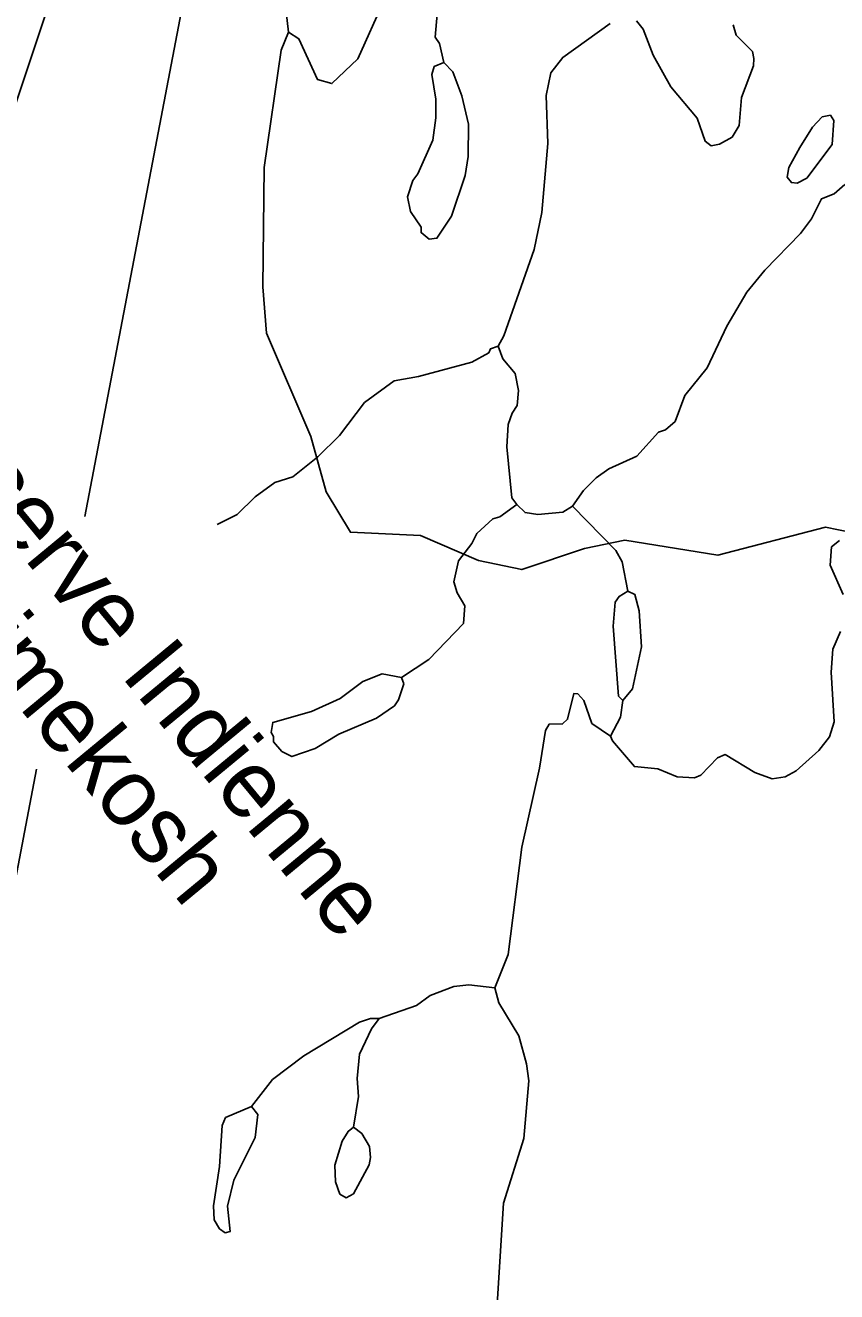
# Model space of a CAD drawing. Extents: x 347312 to 350503, y 6073086 to 6076432.
# Drawn here: x 349676.6 to 349727.5, y 6073873.7 to 6073953.1 of the extents above; entities that cross this region are included whole.
import ezdxf

# ---------------------------------------------------------------- set-up
doc = ezdxf.new("R2010")
doc.units = 0
doc.layers.add('Level 63', color=7, linetype='Continuous')

msp = doc.modelspace()

# ---------------------------------------------------------------- linework, layer by layer
at = {"layer": 'Level 63'}
msp.add_line((349711.71, 6073920.299), (349714.224, 6073920.823), dxfattribs=at)
for points in [[(349680.344, 6073922.306), (349692.276, 6073984.699), (349619.957, 6073998.53), (349601.588, 6073902.476), (349673.907, 6073888.646), (349677.31, 6073906.439)], [(349670.288, 6073937.763), (349671.84, 6073937.31), (349672.811, 6073938.62), (349679.527, 6073958.794), (349681.5, 6073961.168), (349682.809, 6073963.56), (349683.562, 6073964.047), (349684.56, 6073964.294), (349688.619, 6073963.002), (349690.54, 6073961.809), (349691.83, 6073959.629), (349692.683, 6073956.562), (349693.14, 6073952.692)], [(349699.131, 6073954.719), (349697.489, 6073951.034), (349695.853, 6073949.468), (349694.944, 6073949.726), (349693.789, 6073952.283), (349693.14, 6073952.692)], [(349702.532, 6073954.534), (349702.34, 6073952.375), (349702.597, 6073951.982), (349702.883, 6073950.798)], [(349721.028, 6073953.162), (349721.224, 6073952.503), (349722.254, 6073951.474), (349722.325, 6073951.042), (349722.303, 6073950.59), (349721.554, 6073948.588), (349721.411, 6073946.848), (349720.962, 6073946.113), (349720.182, 6073945.659), (349719.657, 6073945.569), (349719.267, 6073945.856), (349718.77, 6073947.308), (349717.119, 6073949.257), (349716.021, 6073951.263), (349715.392, 6073952.881), (349714.97, 6073953.415)], [(349693.14, 6073952.692), (349692.675, 6073951.565), (349691.605, 6073944.209), (349691.516, 6073936.709)], [(349713.315, 6073953.245), (349710.339, 6073951.108), (349709.59, 6073950.136), (349709.303, 6073948.716), (349709.406, 6073945.705), (349709.023, 6073941.389), (349708.538, 6073939.053), (349706.635, 6073933.642), (349706.286, 6073932.986), (349706.587, 6073932.193), (349707.359, 6073931.286), (349707.566, 6073930.201), (349707.488, 6073929.272), (349707.159, 6073928.795)], [(349702.883, 6073950.798), (349702.277, 6073950.535), (349702.128, 6073950.038), (349702.372, 6073948.495), (349702.385, 6073947.312), (349702.191, 6073945.911), (349701.25, 6073943.81), (349700.928, 6073943.394), (349700.597, 6073942.372), (349700.791, 6073941.441), (349701.464, 6073940.454), (349701.455, 6073940.122), (349701.951, 6073939.701), (349702.443, 6073939.764), (349703.361, 6073941.141), (349704.206, 6073943.708), (349704.405, 6073944.896), (349704.43, 6073946.922), (349704.001, 6073948.699), (349703.451, 6073950.216), (349702.883, 6073950.798)], [(349727.149, 6073947.48), (349727.353, 6073947.154), (349727.238, 6073945.653), (349725.659, 6073943.535), (349725.046, 6073943.213), (349724.687, 6073943.255), (349724.423, 6073943.589), (349724.526, 6073944.213), (349725.218, 6073945.465), (349726.002, 6073946.736), (349726.623, 6073947.39), (349727.149, 6073947.48)], [(349707.159, 6073928.795), (349706.923, 6073928.066), (349706.822, 6073926.684), (349707.143, 6073923.467), (349707.46, 6073923.066), (349707.975, 6073922.552), (349708.778, 6073922.428), (349710.341, 6073922.579), (349710.961, 6073922.96), (349711.65, 6073923.94), (349712.439, 6073924.726), (349713.233, 6073925.3), (349714.991, 6073926.094), (349716.348, 6073927.601), (349716.787, 6073927.732), (349717.395, 6073928.267), (349718.009, 6073929.891), (349719.394, 6073931.637), (349720.637, 6073934.248), (349721.885, 6073936.374), (349723.015, 6073937.756), (349725.254, 6073940.069), (349725.937, 6073940.989), (349726.568, 6073942.248), (349727.361, 6073942.549), (349728.035, 6073943.137)], [(349691.516, 6073936.709), (349691.753, 6073933.804), (349694.541, 6073927.33), (349695.498, 6073923.857)], [(349688.657, 6073921.809), (349689.909, 6073922.42), (349691.038, 6073923.529), (349692.266, 6073924.446), (349693.397, 6073924.799), (349694.965, 6073926.039), (349696.335, 6073927.394), (349697.908, 6073929.451), (349699.762, 6073930.81), (349701.279, 6073931.087), (349704.626, 6073931.998), (349705.692, 6073932.571), (349705.813, 6073932.829), (349706.286, 6073932.986)], [(349695.498, 6073923.857), (349697.019, 6073921.317), (349701.416, 6073921.107), (349705.048, 6073919.532), (349707.769, 6073918.972), (349711.71, 6073920.299)], [(349707.46, 6073923.066), (349706.399, 6073922.282), (349705.96, 6073922.151), (349704.945, 6073921.24), (349704.629, 6073920.61), (349703.806, 6073919.525), (349703.499, 6073918.198), (349703.721, 6073917.506), (349704.202, 6073916.693), (349704.103, 6073915.584), (349701.931, 6073913.323), (349700.224, 6073912.19)], [(349710.961, 6073922.96), (349713.662, 6073920.162), (349714.064, 6073919.448), (349714.426, 6073917.619)], [(349714.224, 6073920.823), (349720.079, 6073919.867), (349726.826, 6073921.623), (349729.281, 6073921.125), (349730.398, 6073920.055), (349731.497, 6073918.049), (349733.628, 6073910.623), (349734.502, 6073908.764), (349735.249, 6073908.162), (349736.554, 6073907.404), (349741.055, 6073906.788), (349747.942, 6073907.407), (349751.573, 6073909.194), (349752.623, 6073909.375), (349755.703, 6073908.773), (349766.682, 6073914.094)], [(349727.698, 6073920.795), (349727.198, 6073920.399), (349727.125, 6073919.256), (349727.939, 6073917.405)], [(349714.426, 6073917.619), (349713.872, 6073917.29), (349713.618, 6073916.926), (349713.503, 6073915.425), (349713.838, 6073911.025), (349714.109, 6073910.751)], [(349714.426, 6073917.619), (349714.856, 6073917.418), (349715.13, 6073916.386), (349715.29, 6073914.126), (349714.711, 6073911.498), (349714.109, 6073910.751)], [(349727.76, 6073915.094), (349727.295, 6073913.967), (349727.187, 6073912.526), (349727.369, 6073909.415), (349727.079, 6073908.48), (349726.403, 6073907.62), (349724.98, 6073906.332), (349724.301, 6073905.957), (349723.469, 6073905.842), (349722.395, 6073906.24), (349720.528, 6073907.367), (349720.048, 6073907.15), (349719.012, 6073906.06), (349718.6, 6073905.896), (349717.517, 6073905.962), (349716.304, 6073906.467), (349714.836, 6073906.608), (349713.45, 6073908.223)], [(349700.361, 6073911.811), (349700.224, 6073912.19), (349699.009, 6073912.423), (349697.804, 6073911.958), (349696.376, 6073910.883), (349694.584, 6073910.062), (349692.142, 6073909.378), (349692.039, 6073908.754), (349692.19, 6073908.494), (349692.182, 6073908.162), (349692.717, 6073907.554), (349693.346, 6073907.239), (349694.797, 6073907.736), (349696.297, 6073908.651), (349698.655, 6073909.648), (349699.775, 6073910.425), (349700.03, 6073910.789), (349700.361, 6073911.811)], [(349713.45, 6073908.223), (349713.332, 6073908.51), (349712.154, 6073909.313), (349711.657, 6073910.765), (349711.28, 6073911.172), (349711.041, 6073911.2), (349710.64, 6073909.581), (349710.333, 6073909.284), (349709.483, 6073909.262), (349709.255, 6073908.864), (349708.889, 6073906.515), (349707.766, 6073901.558), (349706.918, 6073894.812), (349706.069, 6073892.73), (349706.323, 6073891.792), (349707.593, 6073889.705), (349708.055, 6073887.956), (349708.202, 6073886.878), (349707.903, 6073883.279), (349706.612, 6073879.22), (349706.188, 6073872.213)], [(349714.109, 6073910.751), (349713.957, 6073909.709), (349713.332, 6073908.51)], [(349698.816, 6073890.791), (349701.153, 6073891.608), (349702.013, 6073892.235), (349703.505, 6073892.818), (349704.455, 6073892.919), (349706.069, 6073892.73)], [(349690.812, 6073885.274), (349692.131, 6073886.968), (349694.092, 6073888.465), (349697.579, 6073890.572), (349698.271, 6073890.794), (349698.816, 6073890.791)], [(349698.816, 6073890.791), (349698.347, 6073890.149), (349697.588, 6073888.572), (349697.44, 6073887.044), (349697.52, 6073885.914), (349697.204, 6073883.983)], [(349691.208, 6073884.773), (349690.812, 6073885.274), (349689.187, 6073884.585), (349688.979, 6073884.095), (349688.798, 6073881.511), (349688.419, 6073879.042), (349688.467, 6073878.158), (349688.797, 6073877.605), (349689.161, 6073877.35), (349689.473, 6073877.435), (349689.296, 6073879.03), (349689.697, 6073880.649), (349691.041, 6073883.339), (349691.208, 6073884.773)], [(349697.733, 6073883.588), (349697.204, 6073883.983), (349696.87, 6073883.719), (349696.494, 6073883.096), (349696.048, 6073881.604), (349696.075, 6073880.541), (349696.35, 6073879.782), (349696.747, 6073879.554), (349697.2, 6073879.804), (349698.2, 6073881.625), (349698.283, 6073882.07), (349698.213, 6073882.775), (349697.733, 6073883.588)]]:
    msp.add_lwpolyline(points, dxfattribs=at)

# ---------------------------------------------------------------- texts
for s, height, p in [('Réserve Indienne', 4.25388, (349668.05, 6073929.88)), ('Matimekosh', 4.2539, (349667.13, 6073921.28))]:
    msp.add_text(s, height=height, rotation=309.56795, dxfattribs=at).set_placement(p)

doc.saveas('drawing.dxf')
